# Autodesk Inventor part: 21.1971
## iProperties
Created: 2007-01
Part Number: 21.1971
Material: UHMW, White
Document SubType Name: Modeling
Designer: Andy Moles
Mass: 0.0734878 g
Surface Area: 1.78694 cm^2
Volume: 0.0781785 cm^3
Density: 0.94 g/cm^3
Description: Plastic Washer 5.8 x 10 x 1.5
Vendor: V
Author: Andy Moles
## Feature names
1. Extrusion1
